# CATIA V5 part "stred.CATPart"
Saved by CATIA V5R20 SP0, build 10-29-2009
Part number: stred
Bounding box of the stored display mesh (mm): x -27.5 to 27.5, y -27.5 to 27.5, z -30.669 to 230
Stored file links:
  C:\Users\joki\Desktop\Belleville spring\stred.CATPart
  Product1.CATProduct
  C:\Users\joki\Desktop\Belleville spring\Assembly.CATProduct
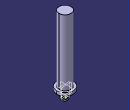
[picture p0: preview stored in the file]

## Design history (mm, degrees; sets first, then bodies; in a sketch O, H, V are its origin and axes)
Body1 (main body)
  Sketch1 on xy-plane, origin (0, 0, 0), H (1, 0, 0), V (0, 1, 0)
    circle A1 centre (0, 0) radius 20
    radius A1 = 20
  Pad1: profile Sketch1, direction (0, 0, 1), length 230
  Plane1: type Offset, RefPlane zx-plane, Offset 5
  Sketch2 on Plane1, origin (0, 5, 0), H (-1, 0, 0), V (0, 0, 1)
    circle A1 centre (0, -17.7329) radius 7.3389
    arc A2 centre (0, -17.7329) radius 13.1065 from (-12.8378, -15.0926) to (12.8378, -15.0926) ccw
    spline S1 through (-12.8378, -15.0926) (-10.8709, -6.6852) (-10.8709, 3.0291)
    spline S2 through (12.8378, -15.0926) (10.8709, -6.6852) (10.8709, 3.0291)
    line L1 (-10.8709, 3.0291) -> (10.8709, 3.0291)
    point P2 (-10.8709, 3.0291)
    point P3 (10.8709, 3.0291)
    point P4 (-12.8378, -15.0926)
    point P5 (12.8378, -15.0926)
    point P6 (-10.8709, 3.0291)
    point P7 (10.8709, 3.0291)
    point P8 (-12.8378, -15.0926)
    point P9 (12.8378, -15.0926)
    coincidence: P6 P2, P7 P3, P8 P4, P9 P5
  Pad2: profile Sketch2, direction (0, -1, 0), length 10
  Fillet1: radius 1, on edge [start face of Pad2 | face of Pad2 from Sketch2.A1]; edge [face of Pad2 from Sketch2.A1 | end face of Pad2]
  Sketch3 on start face of Pad1, origin (0, 0, 0), H (1, 0, 0), V (0, -1, 0)
    circle A1 centre (0, 0) radius 20
    circle A2 centre (0, 0) radius 27.5
    radius A1 = 20
    radius A2 = 27.5
  Pad3: profile Sketch3, direction (0, 0, 1), length 10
